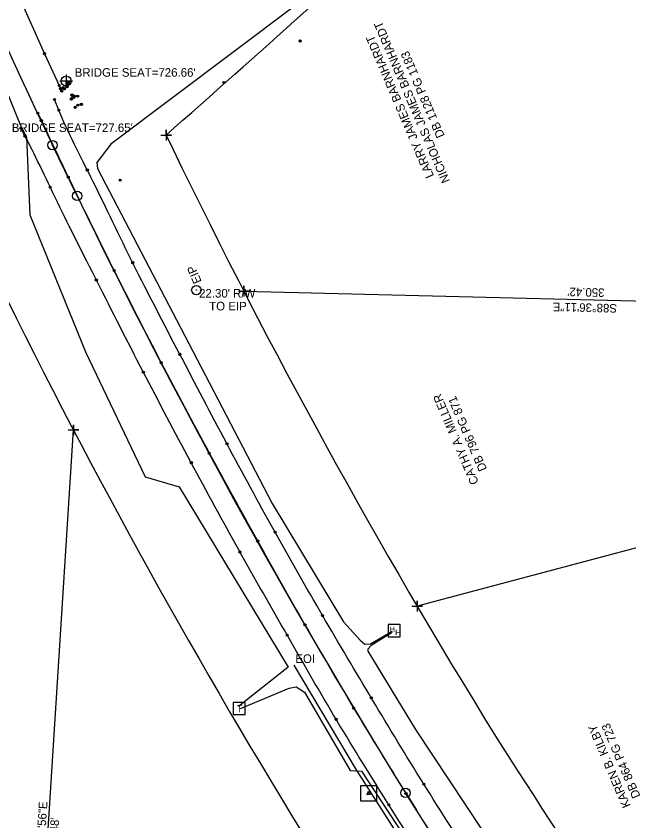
# Model space of a CAD drawing. Extents: x 1550153 to 1552579, y 809637 to 812160.
# Drawn here: x 1551868 to 1552155.6, y 810285.6 to 810663.3 of the extents above; entities that cross this region are included whole.
import ezdxf

# ---------------------------------------------------------------- set-up
doc = ezdxf.new("R2010")
doc.units = 0
for name, color, linetype in [('CTL Secondary Horizontal and Vertical CELL', 7, 'Continuous'), ('Default', 7, 'Continuous'), ('E_NCDOT_Horizontal_Alignment', 7, 'Continuous'), ('E_NCDOT_Horizontal_Alignment_Curve', 7, 'Continuous'), ('E_NCDOT_Horizontal_Alignment_Tick_Label', 7, 'Continuous'), ('Exist DTM Crownline', 7, 'Continuous'), ('Exist Property Corner CELL', 7, 'Continuous'), ('Exist Property Iron Pin CELL', 7, 'Continuous'), ('Exist Property Iron Pin Text', 7, 'Continuous'), ('Exist Property Line', 7, 'Continuous'), ('Exist Property Line Text', 7, 'Continuous'), ('Exist Property Text', 7, 'Continuous'), ('Exist Right of Way Line', 7, 'Continuous'), ('Exist Roads EOP', 7, 'Continuous'), ('Exist Roads EOP Other', 7, 'Continuous'), ('Exist Structure Major Bridge Seat Cogo Point CELL', 7, 'Continuous'), ('Exist Utilities Other Text', 7, 'Continuous'), ('Exist Utilities Other Unknown UG SUE LOS B', 7, 'Continuous'), ('Exist Utilities Telephone Hand Hole CELL', 7, 'Continuous'), ('Exist Utilities Telephone Pedestal CELL', 7, 'Continuous'), ('Exist Utilities Telephone UG Cable SUE LOS B', 7, 'Continuous'), ('Exist Utilities Telephone UG Cable SUE LOS C', 7, 'Continuous'), ('Exist Utilities Telephone UG FO SUE LOS B', 7, 'Continuous')]:
    doc.layers.add(name, color=color, linetype=linetype)

# ---------------------------------------------------------------- blocks, each defined once
blk = doc.blocks.new('SurveyPointCell')
at = {"layer": 'Default'}
for p, q in [((-0.5, 0), (0.5, 0)), ((0, -0.5), (0, 0.5))]:
    blk.add_line(p, q, dxfattribs=at)
blk.add_circle((0, 0), 0.5, dxfattribs=at)
blk = doc.blocks.new('SurveyControlPointCell')
at = {"layer": 'Default'}
for p, q in [((-0.87, -0.5), (0, 1)), ((0, 1), (0.87, -0.5)), ((0.87, -0.5), (-0.87, -0.5))]:
    blk.add_line(p, q, dxfattribs=at)
blk.add_circle((0, 0), 0.5, dxfattribs=at)

msp = doc.modelspace()

# ---------------------------------------------------------------- linework, layer by layer
at = {"layer": 'CTL Secondary Horizontal and Vertical CELL'}
for p, q in [((1552033.43, 810298.53), (1552033.43, 810298.53)), ((1552033.43, 810298.53), (1552033.43, 810298.53)), ((1552033.44, 810298.54), (1552033.44, 810298.54))]:
    msp.add_line(p, q, dxfattribs=at)
for points in [[(1552029.76, 810302.23), (1552037.17, 810302.23), (1552037.17, 810294.81), (1552029.76, 810294.81)], [(1552029.76, 810302.23), (1552037.17, 810302.23), (1552037.17, 810294.81), (1552029.76, 810294.81)], [(1552029.77, 810302.24), (1552037.18, 810302.24), (1552037.18, 810294.81), (1552029.77, 810294.81)]]:
    msp.add_lwpolyline(points, close=True, dxfattribs=at)
at = {"layer": 'Default'}
for p, q in [((1551891.46, 810632.82), (1551891.46, 810632.82)), ((1552033.44, 810298.54), (1552033.44, 810298.54))]:
    msp.add_line(p, q, dxfattribs=at)
msp.add_arc((1544558.52, 818987.58), 11000, 308.905285, 313.48368, dxfattribs=at)
msp.add_arc((1544558.52, 818987.58), 11000, 308.905285, 313.48368, dxfattribs=at)
at = {"layer": 'E_NCDOT_Horizontal_Alignment'}
for p, q in [((1551896.63, 810578.88), (1551885, 810602.78)), ((1552061.08, 810282.48), (1552050.68, 810298.74))]:
    msp.add_line(p, q, dxfattribs=at)
for centre, radius in [((1551885, 810602.78), 2.2), ((1551885, 810602.78), 0.0707), ((1551896.63, 810578.88), 2.2), ((1551896.63, 810578.88), 0.0707), ((1552050.68, 810298.74), 2.2), ((1552050.68, 810298.74), 0.0707)]:
    msp.add_circle(centre, radius, dxfattribs=at)
at = {"layer": 'E_NCDOT_Horizontal_Alignment_Curve'}
for centre, radius, start, end in [((1544245.73, 819324.67), 11459.16, 307.933611, 313.133611), ((1544245.73, 819324.67), 11459.16, 307.933611, 313.133611), ((1554277.17, 811742.97), 2650, 199.47344, 205.4841), ((1554277.17, 811742.97), 2650, 199.47344, 205.4841), ((1554686.42, 811930.56), 3100, 205.85058, 211.76221), ((1554686.42, 811930.56), 3100, 205.85058, 211.76221)]:
    msp.add_arc(centre, radius, start, end, dxfattribs=at)
at = {"layer": 'E_NCDOT_Horizontal_Alignment_Tick_Label'}
msp.add_arc((1544558.52, 818987.58), 11000, 308.905285, 313.48368, dxfattribs=at)
at = {"layer": 'Exist DTM Crownline'}
msp.add_line((1551878.15, 810617.71), (1551879.82, 810614.22), dxfattribs=at)
msp.add_line((1551878.15, 810617.71), (1551879.82, 810614.22), dxfattribs=at)
msp.add_open_spline([(1551879.82, 810614.22), (1551884.05, 810605.39), (1551895.17, 810581.82), (1551913.83, 810543.92), (1551935.88, 810500.73), (1551958.31, 810458.41), (1551980.95, 810417.48), (1552003.45, 810377.54), (1552026.55, 810337.94), (1552050.88, 810298.4), (1552075.94, 810258.8), (1552101.84, 810219.91), (1552127.91, 810181.93), (1552154.01, 810145.21), (1552180.08, 810109.84), (1552206.53, 810074.71), (1552233.39, 810039.85), (1552251.62, 810016.53), (1552260.85, 810005.29)], degree=3, dxfattribs=at)
msp.add_open_spline([(1551879.82, 810614.22), (1551884.05, 810605.39), (1551895.17, 810581.82), (1551913.83, 810543.92), (1551935.88, 810500.73), (1551958.31, 810458.41), (1551980.95, 810417.48), (1552003.45, 810377.54), (1552026.55, 810337.94), (1552050.88, 810298.4), (1552075.94, 810258.8), (1552101.84, 810219.91), (1552127.91, 810181.93), (1552154.01, 810145.21), (1552180.08, 810109.84), (1552206.53, 810074.71), (1552233.39, 810039.85), (1552251.62, 810016.53), (1552260.85, 810005.29)], degree=3, dxfattribs=at)
at = {"layer": 'Exist Property Corner CELL'}
for p, q in [((1551938.35, 810607.43), (1551938.35, 810607.43)), ((1551974.86, 810534.17), (1551974.86, 810534.17)), ((1551894.92, 810469.06), (1551894.92, 810469.06)), ((1552056.21, 810386.38), (1552056.21, 810386.38))]:
    msp.add_line(p, q, dxfattribs=at)
for points in [[(1551935.85, 810607.43), (1551940.85, 810607.43), (1551938.35, 810607.43), (1551938.35, 810609.93), (1551938.35, 810604.93)], [(1551972.36, 810534.17), (1551977.36, 810534.17), (1551974.86, 810534.17), (1551974.86, 810536.67), (1551974.86, 810531.67)], [(1551892.42, 810469.06), (1551897.42, 810469.06), (1551894.92, 810469.06), (1551894.92, 810471.56), (1551894.92, 810466.56)], [(1552053.71, 810386.38), (1552058.71, 810386.38), (1552056.21, 810386.38), (1552056.21, 810388.88), (1552056.21, 810383.88)]]:
    msp.add_lwpolyline(points, dxfattribs=at)
at = {"layer": 'Exist Property Iron Pin CELL'}
for centre, radius in [((1551952.55, 810534.71), 2.2), ((1551952.56, 810534.71), 2.2), ((1551952.56, 810534.71), 2.2), ((1551952.55, 810534.71), 0.0707), ((1551952.56, 810534.71), 0.0707), ((1551952.56, 810534.71), 0.0707)]:
    msp.add_circle(centre, radius, dxfattribs=at)
at = {"layer": 'Exist Property Line'}
for p, q in [((1551974.86, 810534.17), (1552325.17, 810525.63)), ((1551869.88, 810076.38), (1551894.92, 810469.06)), ((1552329.23, 810459.15), (1552056.21, 810386.38))]:
    msp.add_line(p, q, dxfattribs=at)
at = {"layer": 'Exist Right of Way Line'}
msp.add_line((1552093, 810325.36), (1552103.19, 810309.43), dxfattribs=at)
msp.add_lwpolyline([(1551938.35, 810607.43), (1551941.61, 810600.72), (1551941.62, 810600.68)], dxfattribs=at)
for centre, radius, start, end in [((1544245.71, 819324.7), 11626.16, 311.427072, 313.124848), ((1554686.42, 811930.56), 3050, 205.85058, 211.75541), ((1554685.69, 811929.93), 3150, 206.2071, 211.76221), ((1554670.98, 811955.32), 3050, 212.65885, 221.20382)]:
    msp.add_arc(centre, radius, start, end, dxfattribs=at)
at = {"layer": 'Exist Roads EOP'}
for p, q in [((1551888.02, 810619.12), (1551885.97, 810624.14)), ((1551888.02, 810619.12), (1551885.97, 810624.14)), ((1551872.14, 810607.04), (1551870.2, 810610.67)), ((1551872.14, 810607.04), (1551870.2, 810610.67))]:
    msp.add_line(p, q, dxfattribs=at)
for points in [[(1552269.13, 810011.86), (1552259.93, 810023.16), (1552240.78, 810045.4), (1552214.35, 810080.42), (1552187.88, 810115.33), (1552162.14, 810151.01), (1552135.65, 810187.58), (1552109.73, 810225.45), (1552084.16, 810264.07), (1552058.92, 810303.06), (1552035.07, 810342.61), (1552011.65, 810381.94), (1551989.05, 810421.66), (1551966.76, 810462.54), (1551944.71, 810504.82), (1551922.39, 810547.43), (1551904.23, 810585.99), (1551891.95, 810609.53), (1551888.02, 810619.12)], [(1552269.13, 810011.86), (1552259.93, 810023.16), (1552240.78, 810045.4), (1552214.35, 810080.42), (1552187.88, 810115.33), (1552162.14, 810151.01), (1552135.65, 810187.58), (1552109.73, 810225.45), (1552084.16, 810264.07), (1552058.92, 810303.06), (1552035.07, 810342.61), (1552011.65, 810381.94), (1551989.05, 810421.66), (1551966.76, 810462.54), (1551944.71, 810504.82), (1551922.39, 810547.43), (1551904.23, 810585.99), (1551891.95, 810609.53), (1551888.02, 810619.12)], [(1552253.42, 809998.9), (1552244.08, 810010.36), (1552226.02, 810034.01), (1552199.09, 810069.05), (1552172.75, 810104.35), (1552146.51, 810139.68), (1552120.18, 810176.35), (1552094.25, 810214.54), (1552068.09, 810253.47), (1552042.85, 810293.18), (1552018.16, 810332.74), (1551995.33, 810372.57), (1551972.36, 810412.53), (1551950.07, 810453.8), (1551927.46, 810496.24), (1551905.63, 810539.48), (1551886.95, 810576.34), (1551876.35, 810599.18), (1551872.14, 810607.04)], [(1552253.42, 809998.9), (1552244.08, 810010.36), (1552226.02, 810034.01), (1552199.09, 810069.05), (1552172.75, 810104.35), (1552146.51, 810139.68), (1552120.18, 810176.35), (1552094.25, 810214.54), (1552068.09, 810253.47), (1552042.85, 810293.18), (1552018.16, 810332.74), (1551995.33, 810372.57), (1551972.36, 810412.53), (1551950.07, 810453.8), (1551927.46, 810496.24), (1551905.63, 810539.48), (1551886.95, 810576.34), (1551876.35, 810599.18), (1551872.14, 810607.04)]]:
    msp.add_open_spline(points, degree=3, dxfattribs=at)
at = {"layer": 'Exist Roads EOP Other'}
for p, q in [((1551868.68, 810674.18), (1551881.33, 810645.63)), ((1551868.68, 810674.18), (1551881.33, 810645.63)), ((1551881.33, 810645.63), (1551888.17, 810630.74)), ((1551881.33, 810645.63), (1551888.17, 810630.74))]:
    msp.add_line(p, q, dxfattribs=at)
msp.add_arc((1551971.88, 810669.22), 92.13, 204.6882, 205.7098, dxfattribs=at)
msp.add_arc((1551971.88, 810669.22), 92.13, 204.6882, 205.7098, dxfattribs=at)
at = {"layer": 'Exist Structure Major Bridge Seat Cogo Point CELL'}
msp.add_lwpolyline([(1551891.46, 810635.82), (1551891.46, 810629.82), (1551891.46, 810632.82), (1551894.46, 810632.82), (1551888.46, 810632.82)], dxfattribs=at)
msp.add_circle((1551891.46, 810632.82), 2.34, dxfattribs=at)
at = {"layer": 'Exist Utilities Other Unknown UG SUE LOS B'}
msp.add_lwpolyline([(1551998.29, 810358.65), (1552027.49, 810309.53), (1552076.51, 810232.97), (1552119.42, 810170.33), (1552163.65, 810109.03), (1552217.37, 810038.38), (1552288.47, 809950.78)], dxfattribs=at)
at = {"layer": 'Exist Utilities Telephone Hand Hole CELL'}
for p, q in [((1552042.54, 810377.78), (1552042.54, 810372.05)), ((1552048.26, 810377.78), (1552042.54, 810377.78)), ((1552048.26, 810372.05), (1552048.26, 810377.78)), ((1552045.4, 810374.92), (1552045.4, 810374.92)), ((1552042.54, 810372.05), (1552048.26, 810372.05))]:
    msp.add_line(p, q, dxfattribs=at)
at = {"layer": 'Exist Utilities Telephone Pedestal CELL'}
msp.add_line((1551972.63, 810338.36), (1551972.63, 810338.36), dxfattribs=at)
msp.add_lwpolyline([(1551969.91, 810335.53), (1551975.5, 810335.53), (1551975.5, 810341.13), (1551969.91, 810341.13), (1551969.91, 810335.53)], dxfattribs=at)
at = {"layer": 'Exist Utilities Telephone UG Cable SUE LOS B'}
for points in [[(1551869.65, 810612.8), (1551872.88, 810606.48), (1551874.39, 810570.07), (1551900.55, 810505.72), (1551928.57, 810447.11), (1551944.43, 810442.4), (1551995.66, 810357.78), (1551972.31, 810339.29)], [(1551973.26, 810338.34), (1551996.17, 810347.86), (1551999.41, 810348.48), (1552003.26, 810346.04), (1552024.7, 810309.34), (1552030.08, 810308.97), (1552078.4, 810235.23), (1552121.38, 810171.79), (1552166.12, 810110.11), (1552218.44, 810039.34), (1552289.22, 809952.46), (1552328.94, 809901.56), (1552321.82, 809896.99), (1552314.14, 809892.89), (1552309.87, 809891.97)]]:
    msp.add_lwpolyline(points, dxfattribs=at)
at = {"layer": 'Exist Utilities Telephone UG Cable SUE LOS C'}
msp.add_line((1551770.5, 810856.61), (1551869.65, 810612.8), dxfattribs=at)
at = {"layer": 'Exist Utilities Telephone UG FO SUE LOS B'}
for points in [[(1552149.46, 810796.04), (1552145.97, 810799.24), (1552028.19, 810690.34), (1551912.49, 810603.16), (1551905.88, 810594.58), (1551906.11, 810591.78), (1551947.01, 810513.51), (1551988.11, 810434.51), (1552021.62, 810379.02), (1552029.45, 810370.42), (1552031.64, 810368.57), (1552034.29, 810368.77), (1552044.43, 810374.62)], [(1552044.44, 810374.04), (1552034.64, 810367.89), (1552033.1, 810366.21), (1552033.06, 810365.23), (1552055.35, 810328.54), (1552110.28, 810245.54), (1552165.47, 810164.33), (1552213.57, 810097.71), (1552252.14, 810050.46), (1552256.04, 810045.54), (1552256.3, 810042.48), (1552251.81, 810038.38)]]:
    msp.add_lwpolyline(points, dxfattribs=at)

# ---------------------------------------------------------------- block references
at = {"layer": 'Default'}
for name, p in [('SurveyPointCell', (1552001.31, 810651.61)), ('SurveyPointCell', (1552001.31, 810651.61)), ('SurveyPointCell', (1551881.33, 810645.63)), ('SurveyPointCell', (1551881.33, 810645.63)), ('SurveyPointCell', (1551888.17, 810630.74)), ('SurveyPointCell', (1551888.17, 810630.74)), ('SurveyPointCell', (1551890.09, 810629.79)), ('SurveyPointCell', (1551890.09, 810629.79)), ('SurveyPointCell', (1551891.87, 810630.14)), ('SurveyPointCell', (1551891.87, 810630.14)), ('SurveyPointCell', (1551892.14, 810631.58)), ('SurveyPointCell', (1551892.14, 810631.58)), ('SurveyPointCell', (1551892.53, 810631.91)), ('SurveyPointCell', (1551892.53, 810631.91)), ('SurveyPointCell', (1551965.5, 810632.11)), ('SurveyPointCell', (1551965.51, 810632.12)), ('SurveyPointCell', (1551888.87, 810629.25)), ('SurveyPointCell', (1551888.87, 810629.25)), ('SurveyPointCell', (1551889.39, 810628.1)), ('SurveyPointCell', (1551889.39, 810628.1)), ('SurveyPointCell', (1551890.63, 810629.18)), ('SurveyPointCell', (1551890.63, 810629.18)), ('SurveyPointCell', (1551894.22, 810626.23)), ('SurveyPointCell', (1551894.22, 810626.23)), ('SurveyPointCell', (1551895.4, 810625.74)), ('SurveyPointCell', (1551895.4, 810625.74)), ('SurveyPointCell', (1551896.85, 810625.72)), ('SurveyPointCell', (1551896.85, 810625.72)), ('SurveyPointCell', (1551885.97, 810624.14)), ('SurveyPointCell', (1551885.97, 810624.14)), ('SurveyPointCell', (1551893.91, 810624.28)), ('SurveyPointCell', (1551893.91, 810624.28)), ('SurveyPointCell', (1551894.31, 810624.83)), ('SurveyPointCell', (1551894.31, 810624.83)), ('SurveyPointCell', (1551895.06, 810625.16)), ('SurveyPointCell', (1551895.06, 810625.16)), ('SurveyPointCell', (1551898.61, 810621.87)), ('SurveyPointCell', (1551898.61, 810621.87)), ('SurveyPointCell', (1551888.02, 810619.12)), ('SurveyPointCell', (1551888.02, 810619.12)), ('SurveyPointCell', (1551895.71, 810620.48)), ('SurveyPointCell', (1551895.71, 810620.48)), ('SurveyPointCell', (1551896.96, 810621.46)), ('SurveyPointCell', (1551896.96, 810621.46)), ('SurveyPointCell', (1551878.15, 810617.71)), ('SurveyPointCell', (1551878.15, 810617.71)), ('SurveyPointCell', (1551870.2, 810610.67)), ('SurveyPointCell', (1551870.2, 810610.67)), ('SurveyPointCell', (1551879.82, 810614.22)), ('SurveyPointCell', (1551879.82, 810614.22)), ('SurveyPointCell', (1551872.14, 810607.04)), ('SurveyPointCell', (1551872.14, 810607.04)), ('SurveyPointCell', (1551901.4, 810591.05)), ('SurveyPointCell', (1551901.4, 810591.05)), ('SurveyPointCell', (1551892.45, 810587.72)), ('SurveyPointCell', (1551892.45, 810587.72)), ('SurveyPointCell', (1551916.78, 810586.3)), ('SurveyPointCell', (1551916.78, 810586.3)), ('SurveyPointCell', (1551883.96, 810583.03)), ('SurveyPointCell', (1551883.96, 810583.03)), ('SurveyPointCell', (1551922.71, 810547.56)), ('SurveyPointCell', (1551922.71, 810547.56)), ('SurveyPointCell', (1551913.98, 810543.89)), ('SurveyPointCell', (1551913.98, 810543.89)), ('SurveyPointCell', (1551905.65, 810539.42)), ('SurveyPointCell', (1551905.65, 810539.42)), ('SurveyPointCell', (1551944.83, 810504.55)), ('SurveyPointCell', (1551944.83, 810504.55)), ('SurveyPointCell', (1551936.06, 810500.65)), ('SurveyPointCell', (1551936.06, 810500.65)), ('SurveyPointCell', (1551927.69, 810496.2)), ('SurveyPointCell', (1551927.69, 810496.2)), ('SurveyPointCell', (1551966.93, 810462.53)), ('SurveyPointCell', (1551966.93, 810462.53)), ('SurveyPointCell', (1551958.61, 810458.17)), ('SurveyPointCell', (1551958.61, 810458.17)), ('SurveyPointCell', (1551950.18, 810453.7)), ('SurveyPointCell', (1551950.18, 810453.7)), ('SurveyPointCell', (1551989.52, 810421.09)), ('SurveyPointCell', (1551989.52, 810421.09)), ('SurveyPointCell', (1551981.31, 810416.97)), ('SurveyPointCell', (1551981.31, 810416.97)), ('SurveyPointCell', (1551972.98, 810411.83)), ('SurveyPointCell', (1551972.98, 810411.83)), ('SurveyPointCell', (1552011.8, 810381.97)), ('SurveyPointCell', (1552011.8, 810381.97)), ('SurveyPointCell', (1552003.53, 810377.63)), ('SurveyPointCell', (1552003.53, 810377.63)), ('SurveyPointCell', (1552003.53, 810377.62)), ('SurveyPointCell', (1551995.19, 810372.77)), ('SurveyPointCell', (1551995.2, 810372.78)), ('SurveyPointCell', (1551995.2, 810372.78)), ('SurveyPointCell', (1552034.66, 810343.37)), ('SurveyPointCell', (1552034.66, 810343.37)), ('SurveyPointCell', (1552026.41, 810338.53)), ('SurveyPointCell', (1552026.41, 810338.53)), ('SurveyPointCell', (1552018.16, 810333.31)), ('SurveyPointCell', (1552018.16, 810333.31)), ('SurveyPointCell', (1552059.35, 810302.84)), ('SurveyPointCell', (1552059.35, 810302.84)), ('SurveyControlPointCell', (1552033.43, 810298.53)), ('SurveyPointCell', (1552050.97, 810298.44)), ('SurveyPointCell', (1552050.97, 810298.44)), ('SurveyPointCell', (1552042.92, 810293.19)), ('SurveyPointCell', (1552042.92, 810293.19))]:
    msp.add_blockref(name, p, dxfattribs=at)

# ---------------------------------------------------------------- texts
for s, p in [("BRIDGE SEAT=726.66'", (1551895.48, 810634.83)), ("BRIDGE SEAT=727.65'", (1551865.97, 810608.89))]:
    msp.add_text(s, height=4.02, dxfattribs=at).set_placement(p)
at = {"layer": 'Exist Property Iron Pin Text'}
msp.add_text('EIP', height=4.02, rotation=113.1736, dxfattribs=at).set_placement((1551955.15, 810538.74))
at = {"layer": 'Exist Property Line Text'}
for s, rotation, p in [("350.42'", 178.6032, (1552144.16, 810535.48)), ('S88°36\'11"E', 178.6032, (1552150.01, 810528.12)), ('N03°38\'56"E', 86.3511, (1551880.76, 810264.21)), ("393.48'", 86.3511, (1551887.14, 810269.68))]:
    msp.add_text(s, height=4.02, rotation=rotation, dxfattribs=at).set_placement(p)
at = {"layer": 'Exist Property Text'}
for s, p in [('NICHOLAS JAMES BARNHARDT', (1552071.69, 810585.97)), ('LARRY JAMES BARNHARDT', (1552064.15, 810588.28)), ('DB 1128 PG 1183', (1552069.19, 810607.15)), ('CATHY A. MILLER', (1552085.17, 810444.43)), ('DB 796 PG 871', (1552089.03, 810450.73)), ('KAREN B. KILBY', (1552156.44, 810292.76)), ('DB 864 PG 723', (1552161.08, 810297.24))]:
    msp.add_text(s, height=4.02, rotation=113.1736, dxfattribs=at).set_placement(p)
for s, p in [("22.30' R/W", (1551953.85, 810531.2)), ('TO EIP', (1551958.58, 810525.17))]:
    msp.add_text(s, height=4.02, dxfattribs=at).set_placement(p)
at = {"layer": 'Exist Utilities Other Text'}
msp.add_text('EOI', height=4.02, dxfattribs=at).set_placement((1551999.02, 810359.75))
at = {"layer": 'Exist Utilities Telephone Hand Hole CELL'}
for p in [(1552043.32, 810374.32), (1552045.89, 810372.86)]:
    msp.add_text('H', height=2.5, dxfattribs=at).set_placement(p)
at = {"layer": 'Exist Utilities Telephone Pedestal CELL'}
msp.add_text('T', height=3.42, dxfattribs=at).set_placement((1551971.5, 810336.64))

doc.saveas('drawing.dxf')
